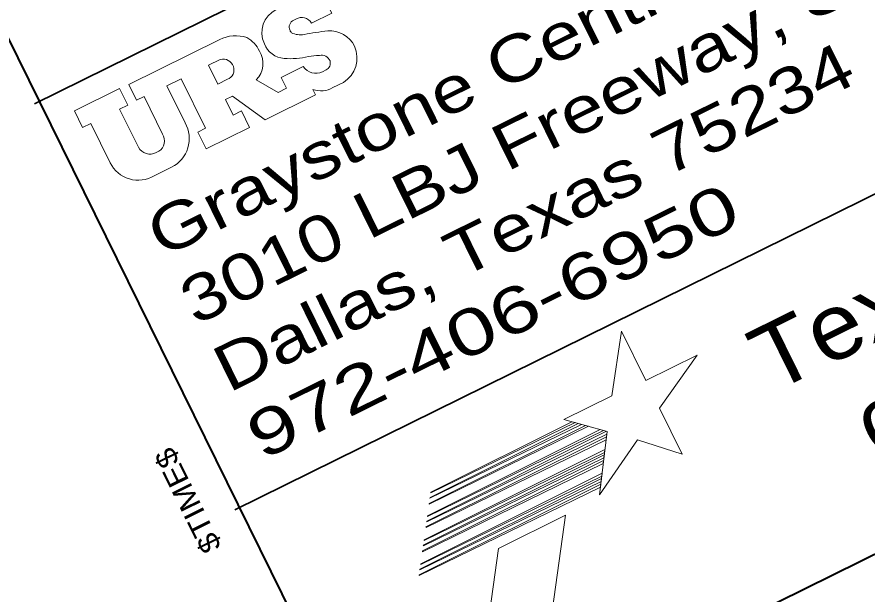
# Model space of a CAD drawing. Extents: x 2356606 to 2371222, y 6973096 to 6982644.
# Drawn here: x 2358140 to 2358383.7, y 6973288.2 to 6973453.7 of the extents above; entities that cross this region are included whole.
import ezdxf
from ezdxf.enums import TextEntityAlignment as Align

# ---------------------------------------------------------------- set-up
doc = ezdxf.new("R2010")
doc.units = 0
doc.header["$LTSCALE"] = 2
for name, color, linetype, lineweight in [('44', 7, 'Continuous', 13), ('62', 7, 'Continuous', 13), ('63', 7, 'Continuous', 13)]:
    doc.layers.add(name, color=color, linetype=linetype, lineweight=lineweight)
doc.layers.add('60', color=7, linetype='Continuous')

msp = doc.modelspace()

# ---------------------------------------------------------------- linework, layer by layer
at = {"layer": '44', "lineweight": 40}
msp.add_lwpolyline([(2358244.847, 6973230.201), (2356740.046, 6976279.238), (2369364.897, 6982510.022)], dxfattribs=at)
at = {"layer": '62', "lineweight": 40}
msp.add_line((2370869.698, 6979460.986), (2358244.847, 6973230.201), dxfattribs=at)
at = {"layer": '62', "lineweight": 35}
for p, q in [((2358728.863, 6973716.998), (2358145.069, 6973428.875)), ((2358557.461, 6973487.691), (2358202.501, 6973312.506))]:
    msp.add_line(p, q, dxfattribs=at)
at = {"layer": '62'}
for p, q in [((2358219.965, 6973453.159), (2358219.35, 6973452.855)), ((2358194.906, 6973439.925), (2358198.282, 6973441.591)), ((2358227.575, 6973437.992), (2358228.635, 6973438.559)), ((2358233.558, 6973435.002), (2358230.568, 6973433.526)), ((2358179.916, 6973414.887), (2358180.688, 6973415.268)), ((2358184.334, 6973410.704), (2358179.354, 6973408.25))]:
    msp.add_line(p, q, dxfattribs=at)
for points in [[(2358221.461, 6973457.508), (2358221.678, 6973457.615), (2358221.074, 6973458.839), (2358226.861, 6973461.695), (2358230.242, 6973454.844), (2358224.455, 6973451.988)], [(2358181.723, 6973420.219), (2358176.437, 6973430.93), (2358174.315, 6973429.882), (2358172.076, 6973434.417), (2358198.118, 6973447.27)], [(2358200.37, 6973435.902), (2358197.573, 6973434.521), (2358194.906, 6973439.925)], [(2358208.542, 6973435.758), (2358214.83, 6973432.119), (2358217.242, 6973433.309), (2358215.718, 6973436.397), (2358222.083, 6973439.538)], [(2358224.841, 6973432.979), (2358225.603, 6973431.436), (2358211.135, 6973424.295), (2358201.789, 6973431.082), (2358199.763, 6973430.083), (2358201.954, 6973425.644), (2358204.365, 6973426.834), (2358206.699, 6973422.106), (2358194.257, 6973415.965), (2358191.876, 6973420.79), (2358194.094, 6973421.885), (2358187.094, 6973436.069), (2358182.946, 6973434.022), (2358188.185, 6973423.408)], [(2358166.721, 6973411.975), (2358161.149, 6973423.265), (2358158.834, 6973422.122), (2358156.501, 6973426.85), (2358169.425, 6973433.229), (2358171.758, 6973428.501), (2358169.443, 6973427.358), (2358174.825, 6973416.455)]]:
    msp.add_lwpolyline(points, dxfattribs=at)
for points in [[(2358313.298, 6973363.722), (2358310.483, 6973345.238), (2358296.723, 6973338.445), (2358309.16, 6973335.041), (2358306.998, 6973316.857), (2358317.906, 6973332.597), (2358330.664, 6973328.536), (2358324.185, 6973341.66), (2358334.96, 6973356.907), (2358320.249, 6973349.638)], [(2358258.173, 6973314.39), (2358302.955, 6973336.733), (2358303.873, 6973336.478), (2358258.179, 6973314.194)], [(2358258.411, 6973316.064), (2358300.915, 6973337.295), (2358301.85, 6973337.029), (2358258.374, 6973315.862)], [(2358258.626, 6973317.619), (2358299.057, 6973337.794), (2358299.981, 6973337.564), (2358258.621, 6973317.405)], [(2358257.458, 6973309.328), (2358308.951, 6973335.072), (2358309.149, 6973335.033), (2358309.056, 6973334.268), (2358257.458, 6973309.107)], [(2358257.689, 6973310.873), (2358307.131, 6973335.591), (2358308.174, 6973335.29), (2358257.677, 6973310.659)], [(2358257.246, 6973307.661), (2358308.981, 6973333.501), (2358308.87, 6973332.609), (2358257.255, 6973307.462)], [(2358256.719, 6973303.978), (2358308.547, 6973329.84), (2358308.444, 6973328.985), (2358256.7, 6973303.778)], [(2358256.482, 6973302.43), (2358308.354, 6973328.31), (2358308.258, 6973327.476), (2358256.488, 6973302.234)], [(2358256.268, 6973300.78), (2358308.156, 6973326.665), (2358308.052, 6973325.818), (2358256.26, 6973300.56)], [(2358255.748, 6973297.088), (2358307.728, 6973323.035), (2358307.626, 6973322.226), (2358255.732, 6973296.882)], [(2358255.305, 6973293.89), (2358307.346, 6973319.868), (2358307.238, 6973319.052), (2358255.27, 6973293.695)], [(2358255.505, 6973295.562), (2358307.552, 6973321.511), (2358307.449, 6973320.712), (2358255.504, 6973295.344)], [(2358278.042, 6973301.506), (2358271.893, 6973257.52), (2358291.086, 6973266.992), (2358297.221, 6973310.978)]]:
    msp.add_lwpolyline(points, close=True, dxfattribs=at)
for centre, radius, start, end in [((2358217.575, 6973449.254), 7.37, 116.59512, 205.42078), ((2358221.607, 6973450.26), 3.331, 31.2441, 119.53115), ((2358220.215, 6973450.867), 2.168, 113.49254, 206.41812), ((2358219.852, 6973450.433), 1.665, 198.57807, 225.70723), ((2358221.17, 6973454.027), 5.391, 242.59812, 282.13548), ((2358251.703, 6973275.283), 175.947, 97.38251, 99.61897), ((2358229.602, 6973441.776), 8.011, 26.74268, 93.62434), ((2358202.704, 6973438.167), 10.193, 71.68598, 116.74432), ((2358201.914, 6973440.569), 8.298, 24.22986, 61.23771), ((2358204.041, 6973440.435), 6.491, 313.90211, 33.05094), ((2358217.053, 6973448.425), 6.564, 200.83249, 265.92335), ((2358229.263, 6973442.008), 8.217, 301.50782, 24.23999), ((2358199.088, 6973438.601), 3.097, 18.24145, 105.09053), ((2358218.431, 6973464.29), 22.488, 265.29523, 283.19444), ((2358228.255, 6973415.113), 27.683, 93.25307, 99.75462), ((2358227.278, 6973440.148), 2.67, 22.69549, 102.85604), ((2358199.383, 6973438.558), 2.833, 290.38106, 20.93943), ((2358225.767, 6973442.094), 4.484, 214.75895, 293.78959), ((2358227.586, 6973440.546), 2.246, 297.83315, 16.35824), ((2358227.118, 6973439.397), 6.809, 250.46341, 300.44168), ((2358180.23, 6973418.884), 9.151, 296.64079, 29.63181), ((2358178.71, 6973418.265), 3.591, 303.41925, 32.96393), ((2358178.171, 6973418.271), 3.807, 208.49718, 297.28605), ((2358174.752, 6973415.929), 8.952, 206.21079, 300.93344)]:
    msp.add_arc(centre, radius, start, end, dxfattribs=at)
at = {"layer": '63', "lineweight": 40}
msp.add_line((2370869.698, 6979460.986), (2358244.847, 6973230.201), dxfattribs=at)
at = {"layer": '63'}
for points in [[(2358313.298, 6973363.722), (2358310.483, 6973345.238), (2358296.723, 6973338.445), (2358309.16, 6973335.041), (2358306.998, 6973316.857), (2358317.906, 6973332.597), (2358330.664, 6973328.536), (2358324.185, 6973341.66), (2358334.96, 6973356.907), (2358320.249, 6973349.638)], [(2358258.173, 6973314.39), (2358302.955, 6973336.733), (2358303.873, 6973336.478), (2358258.179, 6973314.194)], [(2358258.411, 6973316.064), (2358300.915, 6973337.295), (2358301.85, 6973337.029), (2358258.374, 6973315.862)], [(2358258.626, 6973317.619), (2358299.057, 6973337.794), (2358299.981, 6973337.564), (2358258.621, 6973317.405)], [(2358257.458, 6973309.328), (2358308.951, 6973335.072), (2358309.149, 6973335.033), (2358309.056, 6973334.268), (2358257.458, 6973309.107)], [(2358257.689, 6973310.873), (2358307.131, 6973335.591), (2358308.174, 6973335.29), (2358257.677, 6973310.659)], [(2358257.246, 6973307.661), (2358308.981, 6973333.501), (2358308.87, 6973332.609), (2358257.255, 6973307.462)], [(2358256.719, 6973303.978), (2358308.547, 6973329.84), (2358308.444, 6973328.985), (2358256.7, 6973303.778)], [(2358256.482, 6973302.43), (2358308.354, 6973328.31), (2358308.258, 6973327.476), (2358256.488, 6973302.234)], [(2358256.268, 6973300.78), (2358308.156, 6973326.665), (2358308.052, 6973325.818), (2358256.26, 6973300.56)], [(2358255.748, 6973297.088), (2358307.728, 6973323.035), (2358307.626, 6973322.226), (2358255.732, 6973296.882)], [(2358255.305, 6973293.89), (2358307.346, 6973319.868), (2358307.238, 6973319.052), (2358255.27, 6973293.695)], [(2358255.505, 6973295.562), (2358307.552, 6973321.511), (2358307.449, 6973320.712), (2358255.504, 6973295.344)], [(2358278.042, 6973301.506), (2358271.893, 6973257.52), (2358291.086, 6973266.992), (2358297.221, 6973310.978)]]:
    msp.add_lwpolyline(points, close=True, dxfattribs=at)

# ---------------------------------------------------------------- texts
at = {"layer": '60', "width": 1.15}
msp.add_text('$TIME$', height=6, rotation=116.268, dxfattribs=at).set_placement((2358198.814, 6973302.039))
at = {"layer": '62'}
for s, width, p in [('3010 LBJ Freeway, Suite 1300', 1.25, (2358191.148, 6973365.269)), ('Graystone Centre', 1.25, (2358181.612, 6973384.592)), ('Dallas, Texas 75234', 1.25, (2358200.684, 6973345.947)), ('972-406-6950', 1.4, (2358210.221, 6973326.624))]:
    msp.add_text(s, height=13.22, rotation=26.268, dxfattribs=dict(at, width=width)).set_placement(p)
at = {"layer": '62', "width": 1.1}
msp.add_text('Texas Department', height=18.76, rotation=26.268, dxfattribs=at).set_placement((2358458.09, 6973396.009), align=Align.CENTER)
at = {"layer": '62'}
msp.add_text('of Transportation', height=18.76, rotation=26.268, dxfattribs=at).set_placement((2358471.15, 6973369.388), align=Align.CENTER)
at = {"layer": '63', "width": 1.1}
msp.add_text('Texas Department', height=18.76, rotation=26.268, dxfattribs=at).set_placement((2358458.09, 6973396.009), align=Align.CENTER)
at = {"layer": '63'}
msp.add_text('of Transportation', height=18.76, rotation=26.268, dxfattribs=at).set_placement((2358471.15, 6973369.388), align=Align.CENTER)

doc.saveas('drawing.dxf')
